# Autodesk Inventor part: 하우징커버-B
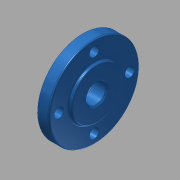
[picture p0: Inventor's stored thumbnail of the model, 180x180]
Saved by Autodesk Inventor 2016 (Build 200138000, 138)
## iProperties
Created: 2018-01
Part Number: 하우징커버-B
Material: 알루미늄 6061
Document SubType Name: Modeling
Designer: mduedu
Density: 2.71 g/cm^3
Appearance: 청록색
Mass: 8.4704 g
Surface Area: 21.4635 cm^2
Volume: 3.12561 cm^3
Author: mduedu
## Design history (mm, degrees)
sketch "스케치1"
  geometry: C1 r 16 at (0, 0); 1 further point
  constraints: 1 centre point, 1 coincident
  dimensions: "d0" = 32 diameter of C1
extrude "돌출1" new body sketch "스케치1" distance "d1" = 4; taper "d2" = 0 deg
sketch "스케치2"
  geometry: C1 r 9 at (0, 0); 1 further point
  constraints: 1 centre point, 1 coincident
  dimensions: "d3" = 18 diameter of C1
extrude "돌출2" join sketch "스케치2" distance "d4" = 1; taper "d5" = 0 deg
fillet "모깎기1" dims "d6" = 0.5
fillet "모깎기2" dims "d7" = 0.5
hole "구멍1" diameter "d10" = 7; stored, may be unused: countersink angle "d14" = 90 deg, drill point angle "d16" = 118 deg; dims "d8" = 10, "d9" = 10, "d11" = 6, "d12" = 4, "d13" = 2, "d15" = 8
chamfer "모따기1" distance "d17" = 0.5; stored, may be unused: second distance "d18" = 2, angle "d19" = 45 deg
sketch "스케치3" dims "d21" = 25
  geometry: 6 further points
  constraints: 2 vertical alignment, 1 coincident, 7 other
  dimensions: "d24" = 360 deg dimension on point (0, 0) point (0, 12.5) (derived)
sketch "스케치4"
  geometry: 4 further points
  constraints: 4 other
hole "구멍2" sketch "스케치4" at (-12.5, 0), (0, -12.5), (12.5, 0), (0, 12.5) diameter "d26" = 3.4; stored, may be unused: countersink angle "d30" = 90 deg, drill point angle "d32" = 0 deg; dims "d27" = 6, "d28" = 4, "d29" = 2, "d31" = 8
node "솔리드1"
